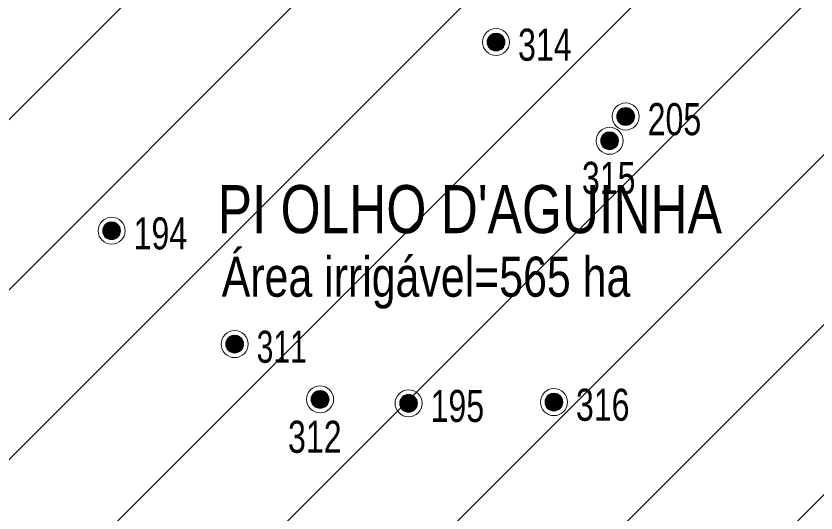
# Model space of a CAD drawing. Extents: x 553962 to 842807, y 8883888 to 9032388.
# Drawn here: x 610250 to 620234, y 8949994 to 8956198 of the extents above; entities that cross this region are included whole.
import ezdxf

# ---------------------------------------------------------------- set-up
doc = ezdxf.new("R2010")
doc.units = 0
doc.header["$LTSCALE"] = 160
for name, color, linetype, lineweight in [('2', 7, 'Continuous', 13), ('30', 7, 'Continuous', 13), ('32', 7, 'Continuous', 13), ('33', 7, 'Continuous', 13)]:
    doc.layers.add(name, color=color, linetype=linetype, lineweight=lineweight)

msp = doc.modelspace()

# ---------------------------------------------------------------- linework, layer by layer
at = {"layer": '30'}
for p, q in [((607896.9, 8952638.5), (617108.2, 8961849.8)), ((609012.2, 8951632.4), (618151, 8960771.3)), ((609922.6, 8950421.5), (619125.3, 8959624.2)), ((610358.4, 8948736), (620168.8, 8958546.4)), ((610930.1, 8947186.4), (621294.6, 8957550.9)), ((612478.6, 8946613.6), (621996.1, 8956131)), ((615167.5, 8947181.2), (623300.4, 8955314)), ((616681.1, 8946573.5), (624604.7, 8954497))]:
    msp.add_line(p, q, dxfattribs=at)
at = {"layer": '32'}
for p, q in [((614015, 8951522), (614015, 8951302)), ((614025, 8951522), (614025, 8951302)), ((614035, 8951522), (614035, 8951302)), ((614045, 8951522), (614045, 8951302)), ((614055, 8951522), (614055, 8951302)), ((614065, 8951522), (614065, 8951302)), ((614075, 8951522), (614075, 8951302)), ((613935, 8951442), (613935, 8951382)), ((613945, 8951462), (613945, 8951362)), ((613955, 8951482), (613955, 8951342)), ((613965, 8951492), (613965, 8951332)), ((613975, 8951502), (613975, 8951322)), ((613985, 8951512), (613985, 8951312)), ((613995, 8951512), (613995, 8951312)), ((614005, 8951512), (614005, 8951312)), ((614085, 8951512), (614085, 8951312)), ((614095, 8951512), (614095, 8951312)), ((614105, 8951502), (614105, 8951322)), ((614115, 8951492), (614115, 8951332)), ((614125, 8951482), (614125, 8951342)), ((614135, 8951472), (614135, 8951352)), ((614145, 8951452), (614145, 8951372))]:
    msp.add_line(p, q, dxfattribs=at)
for radius in [168.7, 111]:
    msp.add_circle((614045, 8951412), radius, dxfattribs=at)
at = {"layer": '33'}
for p, q in [((616141, 8955922), (616141, 8955822)), ((616151, 8955942), (616151, 8955802)), ((616161, 8955952), (616161, 8955792)), ((616171, 8955962), (616171, 8955782)), ((616181, 8955972), (616181, 8955772)), ((616191, 8955972), (616191, 8955772)), ((616201, 8955972), (616201, 8955772)), ((616211, 8955982), (616211, 8955762)), ((616221, 8955982), (616221, 8955762)), ((616231, 8955982), (616231, 8955762)), ((616241, 8955982), (616241, 8955762)), ((616251, 8955982), (616251, 8955762)), ((616261, 8955982), (616261, 8955762)), ((616271, 8955982), (616271, 8955762)), ((616281, 8955972), (616281, 8955772)), ((616291, 8955972), (616291, 8955772)), ((616301, 8955962), (616301, 8955782)), ((616311, 8955952), (616311, 8955792)), ((616321, 8955942), (616321, 8955802)), ((616331, 8955932), (616331, 8955812)), ((616341, 8955912), (616341, 8955832)), ((616131, 8955902), (616131, 8955842)), ((617768, 8955013), (617768, 8954873)), ((617778, 8955023), (617778, 8954863)), ((617788, 8955033), (617788, 8954853)), ((617798, 8955043), (617798, 8954843)), ((617808, 8955043), (617808, 8954843)), ((617818, 8955043), (617818, 8954843)), ((617828, 8955053), (617828, 8954833)), ((617838, 8955053), (617838, 8954833)), ((617848, 8955053), (617848, 8954833)), ((617858, 8955053), (617858, 8954833)), ((617868, 8955053), (617868, 8954833)), ((617878, 8955053), (617878, 8954833)), ((617888, 8955053), (617888, 8954833)), ((617898, 8955043), (617898, 8954843)), ((617908, 8955043), (617908, 8954843)), ((617918, 8955033), (617918, 8954853)), ((617928, 8955023), (617928, 8954863)), ((617938, 8955013), (617938, 8954873)), ((617748, 8954973), (617748, 8954913)), ((617758, 8954993), (617758, 8954893)), ((617948, 8955003), (617948, 8954883)), ((617958, 8954983), (617958, 8954903)), ((617578, 8954720), (617578, 8954560)), ((617588, 8954730), (617588, 8954550)), ((617598, 8954740), (617598, 8954540)), ((617608, 8954740), (617608, 8954540)), ((617618, 8954740), (617618, 8954540)), ((617628, 8954750), (617628, 8954530)), ((617638, 8954750), (617638, 8954530)), ((617648, 8954750), (617648, 8954530)), ((617658, 8954750), (617658, 8954530)), ((617668, 8954750), (617668, 8954530)), ((617678, 8954750), (617678, 8954530)), ((617688, 8954750), (617688, 8954530)), ((617698, 8954740), (617698, 8954540)), ((617708, 8954740), (617708, 8954540)), ((617718, 8954730), (617718, 8954550)), ((617728, 8954720), (617728, 8954560)), ((617548, 8954670), (617548, 8954610)), ((617558, 8954690), (617558, 8954590)), ((617568, 8954710), (617568, 8954570)), ((617738, 8954710), (617738, 8954570)), ((617748, 8954700), (617748, 8954580)), ((617758, 8954680), (617758, 8954600)), ((611383, 8953617), (611383, 8953417)), ((611393, 8953617), (611393, 8953417)), ((611403, 8953617), (611403, 8953417)), ((611413, 8953627), (611413, 8953407)), ((611423, 8953627), (611423, 8953407)), ((611433, 8953627), (611433, 8953407)), ((611443, 8953627), (611443, 8953407)), ((611453, 8953627), (611453, 8953407)), ((611463, 8953627), (611463, 8953407)), ((611473, 8953627), (611473, 8953407)), ((611483, 8953617), (611483, 8953417)), ((611493, 8953617), (611493, 8953417)), ((611333, 8953547), (611333, 8953487)), ((611343, 8953567), (611343, 8953467)), ((611353, 8953587), (611353, 8953447)), ((611363, 8953597), (611363, 8953437)), ((611373, 8953607), (611373, 8953427)), ((611503, 8953607), (611503, 8953427)), ((611513, 8953597), (611513, 8953437)), ((611523, 8953587), (611523, 8953447)), ((611533, 8953577), (611533, 8953457)), ((611543, 8953557), (611543, 8953477)), ((612869, 8952132), (612869, 8952072)), ((612879, 8952152), (612879, 8952052)), ((612889, 8952172), (612889, 8952032)), ((612899, 8952182), (612899, 8952022)), ((612909, 8952192), (612909, 8952012)), ((612919, 8952202), (612919, 8952002)), ((612929, 8952202), (612929, 8952002)), ((612939, 8952202), (612939, 8952002)), ((612949, 8952212), (612949, 8951992)), ((612959, 8952212), (612959, 8951992)), ((612969, 8952212), (612969, 8951992)), ((612979, 8952212), (612979, 8951992)), ((612989, 8952212), (612989, 8951992)), ((612999, 8952212), (612999, 8951992)), ((613009, 8952212), (613009, 8951992)), ((613019, 8952202), (613019, 8952002)), ((613029, 8952202), (613029, 8952002)), ((613039, 8952192), (613039, 8952012)), ((613049, 8952182), (613049, 8952022)), ((613059, 8952172), (613059, 8952032)), ((613069, 8952162), (613069, 8952042)), ((613079, 8952142), (613079, 8952062)), ((615059, 8951433), (615059, 8951293)), ((615069, 8951443), (615069, 8951283)), ((615079, 8951453), (615079, 8951273)), ((615089, 8951463), (615089, 8951263)), ((615099, 8951463), (615099, 8951263)), ((615109, 8951463), (615109, 8951263)), ((615119, 8951473), (615119, 8951253)), ((615129, 8951473), (615129, 8951253)), ((615139, 8951473), (615139, 8951253)), ((615149, 8951473), (615149, 8951253)), ((615159, 8951473), (615159, 8951253)), ((615169, 8951473), (615169, 8951253)), ((615179, 8951473), (615179, 8951253)), ((615189, 8951463), (615189, 8951263)), ((615199, 8951463), (615199, 8951263)), ((615209, 8951453), (615209, 8951273)), ((615219, 8951443), (615219, 8951283)), ((615229, 8951433), (615229, 8951293)), ((615239, 8951423), (615239, 8951303)), ((616863, 8951428), (616863, 8951328)), ((616873, 8951448), (616873, 8951308)), ((616883, 8951458), (616883, 8951298)), ((616893, 8951468), (616893, 8951288)), ((616903, 8951478), (616903, 8951278)), ((616913, 8951478), (616913, 8951278)), ((616923, 8951478), (616923, 8951278)), ((616933, 8951488), (616933, 8951268)), ((616943, 8951488), (616943, 8951268)), ((616953, 8951488), (616953, 8951268)), ((616963, 8951488), (616963, 8951268)), ((616973, 8951488), (616973, 8951268)), ((616983, 8951488), (616983, 8951268)), ((616993, 8951488), (616993, 8951268)), ((617003, 8951478), (617003, 8951278)), ((617013, 8951478), (617013, 8951278)), ((617023, 8951468), (617023, 8951288)), ((617033, 8951458), (617033, 8951298)), ((617043, 8951448), (617043, 8951308)), ((617053, 8951438), (617053, 8951318)), ((617063, 8951418), (617063, 8951338)), ((615039, 8951393), (615039, 8951333)), ((615049, 8951413), (615049, 8951313)), ((615249, 8951403), (615249, 8951323)), ((616853, 8951408), (616853, 8951348))]:
    msp.add_line(p, q, dxfattribs=at)
for centre, radius in [((616241, 8955872), 168.7), ((616241, 8955872), 111), ((617858, 8954943), 168.7), ((617858, 8954943), 111), ((617658, 8954640), 168.7), ((617658, 8954640), 111), ((611443, 8953517), 168.7), ((611443, 8953517), 111), ((612979, 8952102), 168.7), ((612979, 8952102), 111), ((615149, 8951363), 168.7), ((616963, 8951378), 168.7), ((615149, 8951363), 111), ((616963, 8951378), 111)]:
    msp.add_circle(centre, radius, dxfattribs=at)

# ---------------------------------------------------------------- texts
at = {"layer": '2', "width": 0.8}
for s, height, p in [("PI OLHO D'AGUINHA", 600, (612767.1, 8953486.9)), ('Área irrigável=565 ha', 500, (612816.9, 8952693.6))]:
    msp.add_text(s, height=height, dxfattribs=at).set_placement(p)
at = {"layer": '32', "width": 0.75}
msp.add_text('312', height=400, dxfattribs=at).set_placement((613644.1, 8950745.3))
at = {"layer": '33'}
for s, width, p in [('314', 0.75, (616515.2, 8955639.1)), ('205', 0.75, (618132.2, 8954710.1)), ('315', 0.75, (617312.1, 8953976.8)), ('194', 0.75, (611717.2, 8953284.1)), ('311', 0.7, (613253.2, 8951869.1)), ('195', 0.75, (615423.2, 8951130.1)), ('316', 0.75, (617237.2, 8951145.1))]:
    msp.add_text(s, height=400, dxfattribs=dict(at, width=width)).set_placement(p)

doc.saveas('drawing.dxf')
